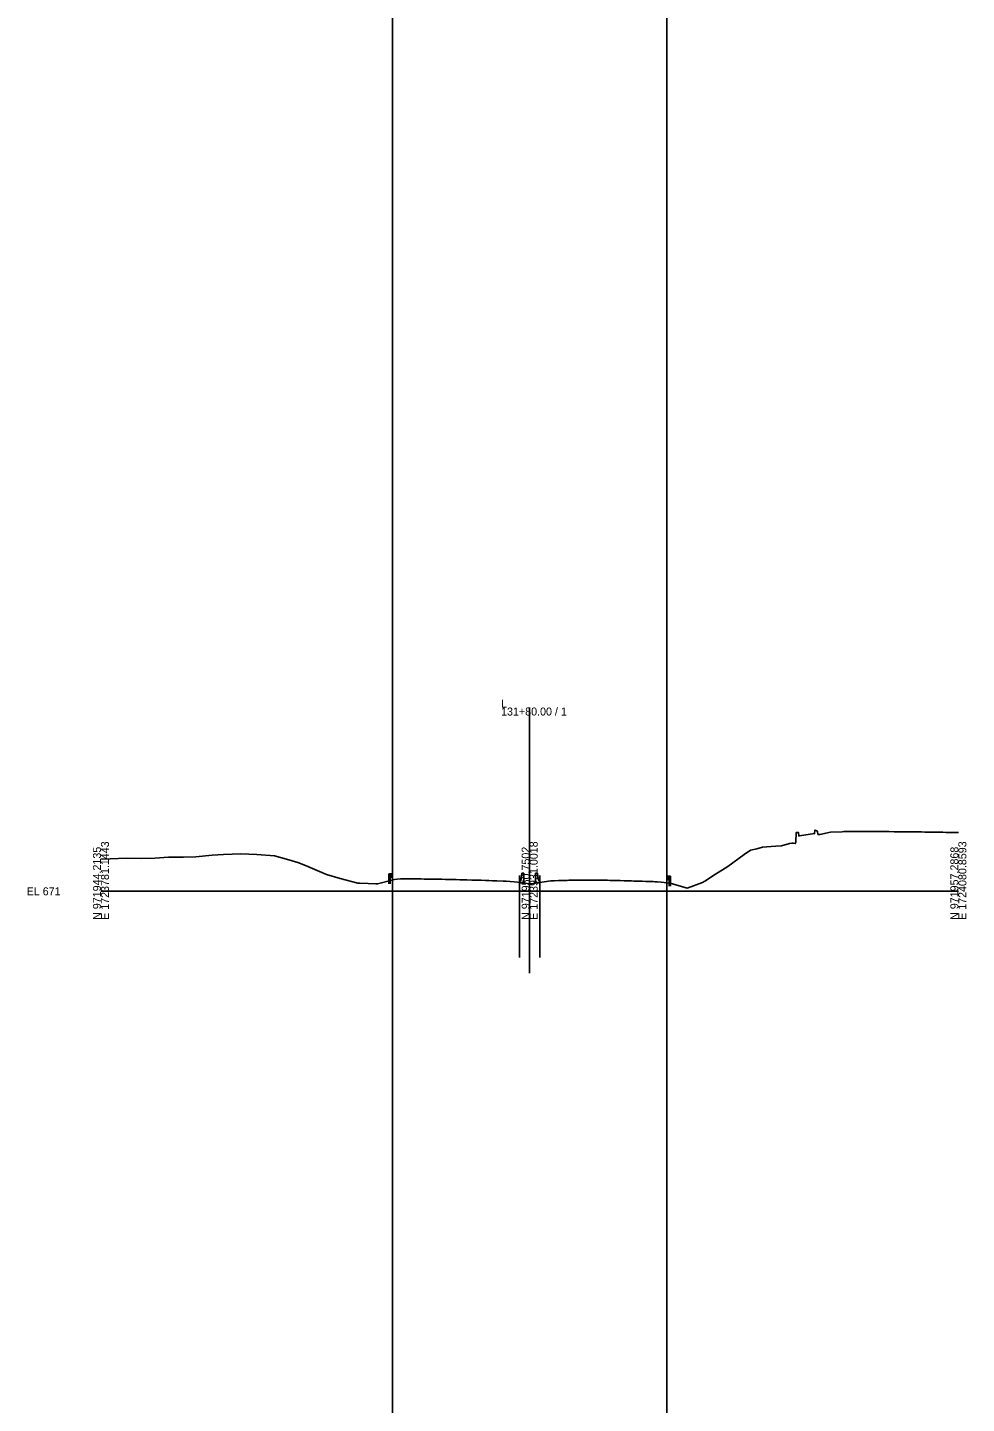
# Model space of a CAD drawing. Extents: x -26 to 303, y -29 to 15026.
# Drawn here: x -25.7 to 302.8, y 7320.8 to 7802.3 of the extents above; entities that cross this region are included whole.
import ezdxf

# ---------------------------------------------------------------- set-up
doc = ezdxf.new("R2010")
doc.units = 0
for name, color, linetype in [('Exist Cross Section Cell', 7, 'Continuous'), ('Exist XS Center Line Elevation Label', 7, 'Continuous'), ('Exist XS Ground Line', 7, 'Continuous'), ('Scratch_Level_0', 7, 'Continuous'), ('Typical Guardrail CELL', 7, 'Continuous'), ('Typical Median Barrier CELL', 7, 'Continuous')]:
    doc.layers.add(name, color=color, linetype=linetype)

msp = doc.modelspace()

# ---------------------------------------------------------------- linework, layer by layer
at = {"layer": 'Exist Cross Section Cell'}
for p, q in [((150, 7500), (150, 7564.33)), ((0, 7500), (150, 7500)), ((150, 7500), (300, 7500))]:
    msp.add_line(p, q, dxfattribs=at)
at = {"layer": 'Exist XS Ground Line'}
msp.add_lwpolyline([(0, 7511.23), (3.23, 7511.33), (8.88, 7511.55), (14.05, 7511.53), (18.89, 7511.61), (23.64, 7511.9), (28.89, 7511.91), (33.24, 7512.11), (38.9, 7512.7), (42.83, 7512.83), (48.91, 7513.08), (54.52, 7512.9), (60.73, 7512.43), (64.89, 7511.22), (68.93, 7510.07), (71.6, 7509.07), (78.94, 7505.86), (83.73, 7504.53), (89.85, 7502.8), (90.6, 7502.8), (93.53, 7502.77), (96.14, 7502.63), (96.81, 7502.58), (101.74, 7503.9), (102.26, 7504.04), (102.66, 7504.11), (103.69, 7504.22), (104.78, 7504.33), (105.6, 7504.34), (106.26, 7504.35), (108.06, 7504.35), (108.88, 7504.35), (110.57, 7504.33), (111.32, 7504.33), (112, 7504.32), (113.08, 7504.3), (114.13, 7504.29), (115.58, 7504.27), (116.75, 7504.26), (118.08, 7504.24), (119.3, 7504.22), (120.56, 7504.19), (122.06, 7504.17), (123.07, 7504.15), (124.25, 7504.12), (125.55, 7504.08), (127.17, 7504.04), (128.05, 7504.02), (129.81, 7503.96), (130.58, 7503.94), (132.42, 7503.87), (133.08, 7503.85), (134.59, 7503.8), (135.72, 7503.76), (137.02, 7503.72), (138.11, 7503.68), (138.49, 7503.67), (140.7, 7503.6), (141.83, 7503.59), (144.63, 7503.33), (146.9, 7503.12), (150, 7502.66), (150.55, 7502.58), (155.04, 7503.29), (157.45, 7503.62), (158.23, 7503.69), (158.59, 7503.7), (160.09, 7503.75), (160.59, 7503.77), (161.2, 7503.79), (163.12, 7503.84), (163.67, 7503.86), (164.37, 7503.88), (164.99, 7503.88), (165.62, 7503.88), (166.46, 7503.88), (168.11, 7503.88), (169.66, 7503.89), (170.64, 7503.9), (171.68, 7503.89), (173.14, 7503.88), (174.46, 7503.88), (175.63, 7503.88), (176.87, 7503.86), (177.21, 7503.86), (178.13, 7503.84), (179.52, 7503.8), (180.61, 7503.77), (181.63, 7503.75), (183.12, 7503.72), (184.73, 7503.66), (185.61, 7503.63), (186.41, 7503.61), (188.12, 7503.57), (189.4, 7503.53), (190.63, 7503.47), (192.43, 7503.43), (193.26, 7503.41), (193.78, 7503.37), (194.73, 7503.3), (196.07, 7503.17), (199.21, 7502.81), (205.14, 7501.13), (210.49, 7503.06), (211.34, 7503.55), (215.06, 7505.99), (219.38, 7508.66), (225.02, 7512.93), (227.24, 7514.35), (229.46, 7514.89), (231.5, 7515.5), (234.56, 7515.68), (236.15, 7515.83), (238.1, 7515.95), (240.89, 7516.69), (241.81, 7516.87), (242.35, 7516.8), (242.92, 7516.68), (243.19, 7517.19), (243.29, 7520.62), (244.04, 7520.59), (244.14, 7519.39), (244.45, 7519.45), (249.7, 7520.22), (249.8, 7521.44), (250.72, 7521.02), (250.87, 7519.94), (251.56, 7519.94), (255.31, 7520.71), (259.32, 7520.87), (259.97, 7520.91), (260.49, 7520.95), (262.24, 7520.98), (262.64, 7520.97), (263.72, 7520.97), (266.14, 7520.94), (268.08, 7520.93), (269.52, 7520.92), (269.96, 7520.92), (270.47, 7520.92), (271.83, 7520.91), (272.5, 7520.91), (273.22, 7520.9), (275.14, 7520.9), (275.71, 7520.89), (277.54, 7520.87), (278.2, 7520.87), (279.94, 7520.85), (280.71, 7520.84), (281.54, 7520.83), (283.22, 7520.81), (284.19, 7520.8), (285.72, 7520.78), (287.14, 7520.77), (288.32, 7520.75), (290.35, 7520.73), (290.7, 7520.72), (293.24, 7520.67), (294.6, 7520.65), (295.71, 7520.63), (296.57, 7520.62), (298.03, 7520.59), (299.39, 7520.56), (300, 7520.56)], dxfattribs=at)
at = {"layer": 'Scratch_Level_0'}
for p, q in [((102, 15009.56), (102, -28.7)), ((198, 15009.56), (198, -28.7)), ((146.46, 7505.5), (146.46, 7476.8)), ((153.54, 7505.5), (153.54, 7476.8)), ((150, 7500), (150, 7471.3)), ((150, 7500), (150, 7471.3))]:
    msp.add_line(p, q, dxfattribs=at)
at = {"layer": 'Typical Guardrail CELL'}
for p, q in [((101.18, 7506.1), (100.68, 7506.1)), ((100.68, 7506.1), (100.68, 7503.62)), ((101.18, 7503.62), (100.68, 7503.62)), ((100.68, 7503.62), (100.68, 7502.61)), ((101.18, 7506.1), (101.18, 7503.62)), ((101.18, 7506.1), (101.68, 7506.1)), ((101.18, 7504.95), (101.68, 7504.95)), ((101.18, 7503.62), (101.18, 7502.61)), ((101.68, 7506.1), (101.68, 7504.95)), ((101.68, 7506.1), (101.97, 7505.9)), ((101.68, 7505.57), (101.97, 7505.77)), ((101.68, 7505.53), (101.68, 7505.57)), ((101.68, 7505.53), (101.68, 7505.48)), ((101.68, 7505.48), (101.97, 7505.28)), ((101.68, 7504.95), (101.97, 7505.15)), ((198.32, 7505.27), (198.03, 7505.06)), ((198.32, 7504.73), (198.03, 7504.94)), ((198.32, 7504.64), (198.03, 7504.44)), ((198.32, 7504.11), (198.03, 7504.31)), ((198.82, 7505.27), (198.32, 7505.27)), ((198.32, 7505.27), (198.32, 7504.11)), ((198.32, 7504.69), (198.32, 7504.73)), ((198.32, 7504.69), (198.32, 7504.64)), ((198.82, 7504.11), (198.32, 7504.11)), ((198.82, 7505.27), (198.82, 7502.78)), ((198.82, 7505.27), (199.32, 7505.27)), ((198.82, 7502.78), (199.32, 7502.78)), ((198.82, 7502.78), (198.82, 7501.77)), ((199.32, 7505.27), (199.32, 7502.78)), ((199.32, 7502.78), (199.32, 7501.77))]:
    msp.add_line(p, q, dxfattribs=at)
for centre, start, end in [((101.92, 7505.84), 304.9888, 54.997), ((101.92, 7505.21), 304.9634, 54.9941), ((198.08, 7505), 125.003, 235.0112), ((198.08, 7504.37), 125.0059, 235.0366)]:
    msp.add_arc(centre, 0.0776, start, end, dxfattribs=at)
at = {"layer": 'Typical Median Barrier CELL'}
for p, q in [((146.46, 7503.37), (146.92, 7504.03)), ((146.46, 7502.95), (146.46, 7503.37)), ((147.96, 7502.95), (146.46, 7502.95)), ((147.07, 7504.42), (147.29, 7506.37)), ((147.29, 7506.37), (147.96, 7506.37)), ((147.96, 7506.37), (147.96, 7502.95)), ((152.71, 7506.37), (152.04, 7506.37)), ((152.04, 7506.37), (152.04, 7502.95)), ((152.04, 7502.95), (153.54, 7502.95)), ((152.93, 7504.42), (152.71, 7506.37)), ((153.54, 7503.37), (153.08, 7504.03)), ((153.54, 7502.95), (153.54, 7503.37))]:
    msp.add_line(p, q, dxfattribs=at)
for centre, start, end in [((146.24, 7504.51), 325.0039, 353.9447), ((153.76, 7504.51), 186.0553, 214.9961)]:
    msp.add_arc(centre, 0.833, start, end, dxfattribs=at)

# ---------------------------------------------------------------- texts
at = {"layer": 'Exist Cross Section Cell'}
for s, p in [('L', (140, 7564.33)), ('131+80.00 / 1', (140, 7561.53)), ('EL 671', (-26, 7498.6))]:
    msp.add_text(s, height=2.8, dxfattribs=at).set_placement(p)
for s, p in [('E 1723781.1443', (2.8, 7490)), ('E 1723931.0018', (152.8, 7490)), ('E 1724080.8593', (302.8, 7490)), ('N 971944.2135', (0, 7490)), ('N 971950.7502', (150, 7490)), ('N 971957.2868', (300, 7490))]:
    msp.add_text(s, height=2.8, rotation=90, dxfattribs=at).set_placement(p)
at = {"layer": 'Exist XS Center Line Elevation Label'}
msp.add_text('673.66', height=0.18, dxfattribs=at).set_placement((149.62, 7502.17))

doc.saveas('drawing.dxf')
